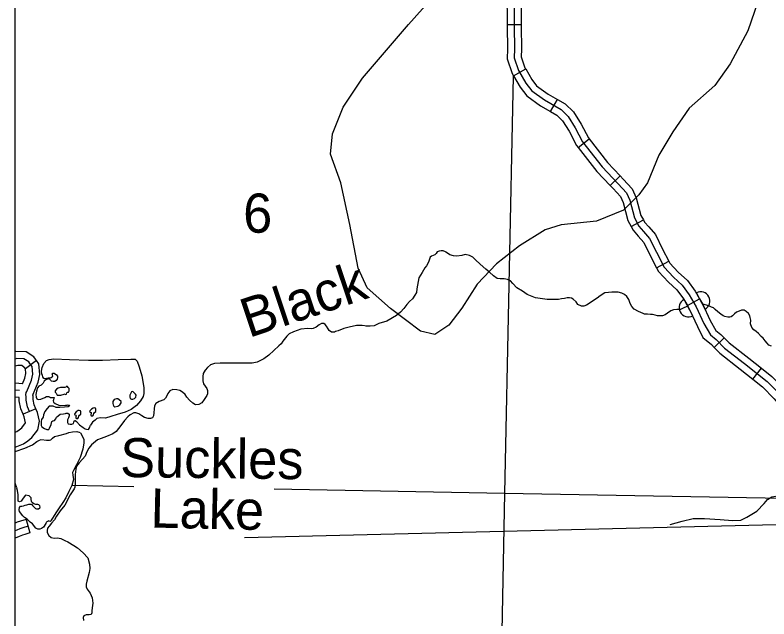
# Model space of a CAD drawing. Extents: x 8749 to 11879, y 13275 to 15339.
# Drawn here: x 9678.1 to 9840.8, y 13844.4 to 13974.8 of the extents above; entities that cross this region are included whole.
import ezdxf

# ---------------------------------------------------------------- set-up
doc = ezdxf.new("R2010")
doc.units = 0
for name, color, linetype in [('Level 31', 7, 'Continuous'), ('Level 32', 7, 'Continuous'), ('Level 35', 7, 'Continuous'), ('Level 38', 7, 'Continuous'), ('Level 45', 7, 'Continuous'), ('Level 5', 7, 'Continuous'), ('R_Draft', 7, 'Continuous')]:
    doc.layers.add(name, color=color, linetype=linetype)

msp = doc.modelspace()

# ---------------------------------------------------------------- linework, layer by layer
at = {"layer": 'Level 31'}
msp.add_lwpolyline([(9727.58, 13861.97), (9895.28, 13866.07), (10058.91, 13870.32)], dxfattribs=at)
at = {"layer": 'Level 32'}
for p, q in [((9784.28, 13972.75), (9787.28, 13972.75)), ((9785.67, 13961.66), (9788.27, 13963.14)), ((9793.65, 13953.94), (9795.15, 13956.53)), ((9799.6, 13946.17), (9801.97, 13948.02)), ((9806.48, 13937.99), (9808.67, 13940.05)), ((9811.01, 13929.15), (9813.67, 13930.54)), ((9816.51, 13920.22), (9819.17, 13921.61)), ((9823.16, 13912.06), (9825.78, 13913.53)), ((9828.97, 13902.97), (9831.11, 13905.08)), ((9682.72, 13900.16), (9680.3, 13898.38)), ((9837.28, 13896.18), (9839.14, 13898.53)), ((9682.58, 13889.77), (9679.82, 13888.58)), ((9682.58, 13889.77), (9679.82, 13888.58))]:
    msp.add_line(p, q, dxfattribs=at)
for points in [[(9782.89, 13998.9), (9783.44, 13993.92), (9784.06, 13988.9), (9784.57, 13984.55), (9785.15, 13981.25), (9785.48, 13978.4), (9785.78, 13976.08), (9785.78, 13972.31), (9785.85, 13967.45)], [(9839.72, 13981.69), (9836.2, 13971.38), (9832.42, 13964.24), (9829.06, 13959.55), (9823.51, 13954.7), (9820, 13949.59), (9816.98, 13944.54), (9814.57, 13938.56), (9812.67, 13935.94), (9809.35, 13932.65), (9803.52, 13930.28), (9795.91, 13929.5), (9792.44, 13928.4), (9786.93, 13924.96), (9781.98, 13921.09), (9777.78, 13916.7), (9774.47, 13911.52), (9771.7, 13907.8), (9768.63, 13905.84), (9765.55, 13906.49), (9759.08, 13911.44), (9754.08, 13915.87), (9752.09, 13920.14), (9750.31, 13929.54), (9748.38, 13938.52), (9746.16, 13944.77), (9746.56, 13949.12), (9748.9, 13954.89), (9753.08, 13961.18), (9762.95, 13972.72), (9779.34, 13991.12)], [(9786.28, 13983.5), (9786.64, 13981.47), (9786.97, 13978.58), (9787.28, 13976.18), (9787.28, 13972.75)], [(9783.33, 13982.98), (9783.67, 13981.03), (9783.99, 13978.22), (9784.28, 13975.99), (9784.28, 13972.75)], [(9784.28, 13972.75), (9784.28, 13972.3), (9784.35, 13967.45), (9784.3, 13965.29), (9785.38, 13962.17), (9785.67, 13961.66)], [(9787.28, 13972.75), (9787.28, 13972.32), (9787.35, 13967.44), (9787.31, 13965.76), (9788.12, 13963.41), (9788.27, 13963.14)], [(9785.85, 13967.45), (9785.81, 13965.53), (9786.75, 13962.79), (9788.31, 13960.05), (9789.58, 13958.43), (9792.32, 13956.44), (9795.9, 13954.36), (9797.41, 13952.9), (9798.92, 13950.45), (9800.53, 13947.42), (9804.77, 13941.99), (9808.21, 13938.34)], [(9788.27, 13963.14), (9789.56, 13960.89), (9790.63, 13959.52), (9793.14, 13957.7), (9795.15, 13956.53)], [(9785.67, 13961.66), (9787.06, 13959.21), (9788.53, 13957.33), (9791.5, 13955.18), (9793.65, 13953.94)], [(9795.15, 13956.53), (9796.81, 13955.57), (9798.59, 13953.85), (9800.22, 13951.19), (9801.79, 13948.24), (9801.97, 13948.02)], [(9793.65, 13953.94), (9794.99, 13953.16), (9796.23, 13951.96), (9797.62, 13949.7), (9799.26, 13946.6), (9799.6, 13946.17)], [(9801.97, 13948.02), (9805.91, 13942.97), (9808.67, 13940.05)], [(9799.6, 13946.17), (9803.63, 13941.02), (9806.48, 13937.99)], [(9808.67, 13940.05), (9809.31, 13939.37), (9811.27, 13937.24), (9812.13, 13935.3), (9813.15, 13931.53), (9813.67, 13930.54)], [(9806.48, 13937.99), (9807.11, 13937.32), (9808.73, 13935.57), (9809.29, 13934.3), (9810.34, 13930.42), (9811.01, 13929.15)], [(9808.21, 13938.34), (9810, 13936.41), (9810.71, 13934.8), (9811.75, 13930.98), (9812.69, 13929.18), (9813.68, 13928.05), (9815, 13926.54), (9816.46, 13923.56), (9818.16, 13920.31), (9820.14, 13918.18), (9822.03, 13916.43), (9823.58, 13914.36), (9825.05, 13911.76), (9826.73, 13908.15)], [(9813.67, 13930.54), (9813.94, 13930.04), (9814.81, 13929.04), (9816.26, 13927.38), (9817.8, 13924.24), (9819.17, 13921.61)], [(9811.01, 13929.15), (9811.44, 13928.33), (9812.55, 13927.06), (9813.74, 13925.7), (9815.13, 13922.89), (9816.51, 13920.22)], [(9819.17, 13921.61), (9819.4, 13921.18), (9821.2, 13919.24), (9823.15, 13917.44), (9824.84, 13915.19), (9825.78, 13913.53)], [(9816.51, 13920.22), (9816.93, 13919.43), (9819.08, 13917.12), (9820.91, 13915.42), (9822.33, 13913.54), (9823.16, 13912.06)], [(9825.78, 13913.53), (9826.39, 13912.44), (9828.05, 13908.86), (9829.32, 13906.7), (9830.37, 13905.83), (9831.11, 13905.08)], [(9823.16, 13912.06), (9823.72, 13911.07), (9825.37, 13907.51), (9826.46, 13905.16), (9828.34, 13903.62), (9828.97, 13902.97)], [(9826.72, 13908.16), (9828.16, 13905.71), (9829.35, 13904.73), (9831.18, 13902.86), (9835.47, 13899.52), (9840.37, 13895.66)], [(9831.11, 13905.08), (9832.18, 13903.99), (9836.4, 13900.7), (9839.14, 13898.53)], [(9682.72, 13900.16), (9682.51, 13900.45), (9682.1, 13901), (9680.47, 13902.05), (9678.28, 13902.12), (9678.09, 13902.07)], [(9828.97, 13902.97), (9830.18, 13901.74), (9834.54, 13898.34), (9837.28, 13896.18)], [(9681.3, 13899.56), (9681.05, 13899.89), (9680.01, 13900.57), (9678.47, 13900.61), (9678.09, 13900.51)], [(9682.58, 13889.77), (9682.2, 13890.65), (9681.99, 13891.8), (9681.97, 13892.52), (9681.94, 13892.73), (9681.97, 13892.9), (9681.98, 13892.93), (9683.04, 13895.48), (9683.41, 13897.14), (9683.22, 13899.47), (9682.72, 13900.16)], [(9680.3, 13898.38), (9680.09, 13898.67), (9680, 13898.78), (9679.55, 13899.08), (9678.66, 13899.11), (9678.09, 13898.95)], [(9681.2, 13889.17), (9680.75, 13890.22), (9680.49, 13891.64), (9680.47, 13892.4), (9680.43, 13892.75), (9680.51, 13893.31), (9680.59, 13893.5), (9681.6, 13895.93), (9681.9, 13897.25), (9681.76, 13898.92), (9681.3, 13899.56)], [(9839.14, 13898.53), (9841.38, 13896.77), (9844.13, 13893.96), (9846.75, 13890.81)], [(9679.67, 13895.18), (9680.17, 13896.38), (9680.38, 13897.35), (9680.3, 13898.38), (9680.3, 13898.38)], [(9679.67, 13895.18), (9678.09, 13895.28)], [(9837.28, 13896.18), (9839.37, 13894.54), (9841.9, 13891.95), (9844.44, 13888.89)], [(9840.37, 13895.66), (9843.01, 13892.96), (9845.82, 13889.58), (9847.7, 13886.94), (9848.86, 13884.67), (9849.4, 13882.86), (9850.29, 13879.86), (9851.15, 13876.65), (9852.29, 13873.76), (9853.5, 13870.63), (9854.28, 13867.61)], [(9679.06, 13893.72), (9678.09, 13893.78)], [(9678.98, 13892.22), (9678.09, 13892.28)], [(9679.82, 13888.58), (9679.3, 13889.78), (9679, 13891.49), (9678.98, 13892.22)], [(9678.09, 13881.5), (9679.92, 13882.17), (9680.84, 13882.84), (9681.72, 13883.59), (9682.98, 13885.19), (9683.33, 13887.12), (9682.93, 13888.96), (9682.58, 13889.77)], [(9678.09, 13884.7), (9678.5, 13884.85), (9678.98, 13885.2), (9679.55, 13885.68), (9680.35, 13886.7), (9680.06, 13888.03), (9679.82, 13888.58)]]:
    msp.add_lwpolyline(points, dxfattribs=at)
at = {"layer": 'Level 35'}
for points in [[(9775.21, 13923.05), (9774.48, 13922.83), (9773.42, 13922.72), (9772.72, 13922.77), (9771.92, 13923.04), (9771.43, 13923.36), (9771.03, 13923.58), (9770.94, 13923.63), (9770.46, 13923.88), (9770, 13923.9), (9769.6, 13923.8), (9769.17, 13923.66), (9768.98, 13923.26), (9768.68, 13923.01), (9768.33, 13922.83), (9767.95, 13922.72), (9767.66, 13922.47), (9767.52, 13922.1), (9767.36, 13921.61), (9767.14, 13921.1), (9766.9, 13920.64), (9766.47, 13920.18), (9765.93, 13919.21), (9765.23, 13918.02), (9764.91, 13916.46), (9764.8, 13915.65), (9764.72, 13914.84), (9764.37, 13914.27), (9763.83, 13913.52), (9763.21, 13912.95)], [(9792.91, 13913.34), (9790.41, 13913.72), (9788.58, 13914.42), (9787.55, 13915.17), (9786.37, 13915.85), (9785.5, 13916.85), (9785.02, 13917.36), (9784.34, 13917.66), (9783.64, 13917.79), (9782.75, 13917.82), (9782.08, 13917.9), (9781.33, 13918.44), (9780.44, 13919.25), (9779.68, 13919.9), (9778.41, 13921), (9777.47, 13921.92), (9776.85, 13922.49), (9776.15, 13922.84), (9775.21, 13923.05)], [(9813.63, 13910.33), (9812.59, 13910.8), (9811.7, 13911.26), (9811.18, 13911.83), (9810.81, 13912.5), (9810.51, 13913.39), (9810.11, 13914.01), (9809.59, 13914.42), (9809.03, 13914.74), (9808.19, 13914.93), (9806.87, 13914.96), (9806.17, 13914.88), (9805.36, 13914.82), (9804.37, 13914.15), (9803.66, 13913.66), (9802.88, 13913.18), (9801.94, 13912.48), (9801.37, 13912.15), (9800.83, 13911.91), (9800.3, 13911.91), (9799.54, 13912.31), (9799.16, 13912.83), (9798.49, 13913.42), (9798.17, 13913.64), (9797.71, 13913.72), (9797.22, 13913.72), (9796.63, 13913.58), (9796.01, 13913.47), (9795.34, 13913.39), (9794.66, 13913.34), (9793.99, 13913.34), (9792.91, 13913.34)], [(9763.21, 13912.95), (9762.63, 13912.25), (9761.96, 13911.44), (9761.28, 13910.65), (9760.37, 13909.9), (9758.29, 13908.71), (9756.59, 13908.17), (9755.57, 13907.69), (9754.68, 13907.61), (9754.06, 13907.58), (9753.81, 13907.58)], [(9823.24, 13911.91), (9822.42, 13911.55), (9821.69, 13911.17), (9820.91, 13911.17), (9820.13, 13911.14), (9819.56, 13910.95), (9818.89, 13910.44), (9818.38, 13910.06), (9817.76, 13909.87), (9817.19, 13909.85), (9816.71, 13909.87), (9816.19, 13909.98), (9815.65, 13910.09), (9815.17, 13910.09), (9814.58, 13910.22), (9814.33, 13910.2), (9813.88, 13910.2), (9813.63, 13910.33)], [(9836.65, 13909.83), (9836.38, 13910.36), (9835.87, 13910.79), (9835.38, 13911.09), (9834.85, 13911.09), (9834.33, 13910.87), (9833.79, 13910.65), (9833.34, 13910.28), (9832.93, 13909.85), (9832.58, 13909.63), (9832.31, 13909.58), (9831.88, 13909.58), (9831.26, 13909.71), (9830.88, 13909.85), (9830.37, 13910.22), (9829.72, 13910.71), (9829.13, 13911.19), (9828.78, 13911.55), (9828.35, 13911.73), (9827.92, 13911.9), (9826.34, 13912.46)], [(9841.32, 13903.25), (9840.75, 13903.52), (9840.35, 13903.92), (9839.94, 13904.41), (9839.48, 13905), (9839.11, 13905.38), (9838.51, 13906.03), (9838.03, 13906.43), (9837.52, 13906.84), (9837.08, 13907.35), (9836.81, 13908.13), (9836.84, 13908.91), (9836.73, 13909.48), (9836.65, 13909.83)], [(9754.06, 13907.58), (9752.98, 13907.73), (9751.76, 13907.73), (9750.2, 13907.38), (9749.04, 13907.09), (9747.83, 13906.6), (9747.24, 13906.47), (9746.99, 13906.33), (9746.35, 13906.33), (9745.86, 13906.65), (9745.65, 13907.06), (9745.32, 13907.6), (9745.03, 13907.98), (9744.7, 13908.19), (9744.22, 13908.19), (9743.71, 13907.9), (9743.06, 13907.41), (9742.44, 13907.09), (9741.95, 13907.01), (9741.23, 13907.09), (9739.74, 13906.98), (9738.18, 13906.36), (9737.26, 13905.93), (9736.7, 13905.47), (9735.83, 13904.39), (9735.51, 13903.77), (9735.03, 13903.36)], [(9735.03, 13903.36), (9732.85, 13901.37), (9731.74, 13900.56), (9730.29, 13899.84), (9729.26, 13899.65), (9727.19, 13899.59), (9725.98, 13899.65), (9724.12, 13899.65)], [(9683.96, 13897.11), (9683.88, 13897.25), (9683.8, 13897.92), (9683.91, 13898.65), (9684.26, 13899.54), (9684.85, 13900.16), (9685.42, 13900.41), (9686.42, 13900.54), (9689.84, 13900.41), (9693.94, 13900.27), (9696.93, 13900.27), (9700.3, 13900.41), (9703.1, 13900.46)], [(9703.1, 13900.46), (9704.01, 13900.49), (9704.45, 13900.03), (9704.88, 13898.79), (9705.42, 13896.87), (9705.85, 13894.39), (9705.87, 13893.07), (9705.69, 13892.44), (9705.15, 13891.5), (9704.31, 13890.45), (9703.15, 13889.58), (9701.83, 13889.04), (9700.11, 13888.53), (9698.73, 13888.1), (9697.57, 13887.75), (9696.55, 13887.78), (9695.74, 13887.67), (9695.34, 13887.29), (9694.77, 13886.89), (9694.39, 13886.21)], [(9724.12, 13899.65), (9722.31, 13899.6), (9721.1, 13899.52), (9720.24, 13899.25), (9719.62, 13898.68), (9719.08, 13898.12), (9718.65, 13897.39), (9718.62, 13896.71), (9718.62, 13895.82), (9718.78, 13895.12), (9719.48, 13894.18), (9719.62, 13893.74), (9719.62, 13893.02), (9719.48, 13892.64), (9718.89, 13891.75), (9718.38, 13891.02), (9717.71, 13890.72), (9717.03, 13890.64), (9716.41, 13890.97), (9715.71, 13891.64), (9715.12, 13892.31), (9714.79, 13892.85), (9714.2, 13893.39), (9713.66, 13893.69), (9712.96, 13893.85), (9712.13, 13893.91), (9711.45, 13893.61), (9711.02, 13893.04), (9710.81, 13892.56), (9710.54, 13892.04), (9710.16, 13891.72)], [(9683.88, 13897.25), (9684.1, 13896.49), (9684.42, 13896.3), (9685.23, 13896.44), (9685.69, 13896.44), (9685.87, 13896.55), (9686.2, 13896.79), (9686.14, 13897.11), (9686.09, 13897.33), (9686.23, 13897.46), (9686.55, 13897.44), (9687.01, 13897.09), (9687.22, 13896.82), (9687.22, 13896.55), (9687.2, 13896.14), (9686.98, 13895.9), (9686.63, 13895.66), (9686.28, 13895.63), (9685.96, 13895.76), (9685.71, 13895.93), (9685.63, 13896.06), (9685.23, 13896.22), (9684.74, 13896.01), (9684.37, 13895.76), (9684.15, 13895.33), (9683.69, 13894.9), (9683.21, 13894.68), (9682.91, 13894.28), (9682.72, 13893.55), (9682.56, 13892.85), (9682.61, 13892.28), (9682.75, 13891.91), (9683.1, 13891.74), (9683.66, 13891.82), (9684.5, 13892.23), (9684.9, 13892.42), (9685.28, 13892.44), (9685.52, 13892.34), (9685.74, 13892.2), (9686.12, 13892.18), (9686.52, 13892.23), (9686.31, 13891.47), (9686.41, 13891.18), (9686.76, 13890.91), (9687.55, 13890.58), (9687.98, 13890.47), (9688.95, 13890.58), (9689.35, 13890.58), (9689.54, 13890.61), (9689.76, 13890.58)], [(9688.52, 13894.33), (9687.92, 13894.39), (9687.36, 13894.23), (9687.01, 13894.01), (9686.76, 13893.66), (9686.74, 13893.34), (9686.93, 13893.15), (9687.17, 13892.74), (9687.3, 13892.74), (9687.95, 13892.74), (9688.68, 13892.9), (9688.92, 13892.98), (9689, 13892.88), (9689.19, 13892.9), (9689.16, 13893.04), (9689.32, 13893.36), (9689.62, 13893.39), (9689.76, 13893.61), (9689.78, 13894.06), (9689.76, 13894.17), (9689.59, 13894.28), (9689.54, 13894.39), (9689.43, 13894.6), (9689.22, 13894.68), (9689.06, 13894.44), (9688.84, 13894.36), (9688.52, 13894.33)], [(9703.13, 13893.25), (9702.87, 13892.68), (9702.86, 13892.34), (9702.93, 13892.01), (9703.2, 13891.81), (9703.53, 13891.81), (9703.84, 13892.01), (9704.15, 13892.31), (9704.18, 13892.74), (9704.09, 13892.94), (9703.78, 13893.21), (9703.58, 13893.45), (9703.4, 13893.51), (9703.23, 13893.43), (9703.13, 13893.25)], [(9689.76, 13890.58), (9689.81, 13890.39), (9689.56, 13890.17), (9688.78, 13890.09), (9687.73, 13890.06), (9686.92, 13890.06), (9686.33, 13890.31), (9685.87, 13890.33), (9685.47, 13890.33), (9685.04, 13889.85), (9684.52, 13889.15), (9684.23, 13888.44), (9684.12, 13887.93), (9683.82, 13887.47), (9683.74, 13886.99), (9683.74, 13886.39), (9683.69, 13886.15), (9683.85, 13885.85), (9684.44, 13885.48), (9684.93, 13885.26), (9685.36, 13885.29), (9685.49, 13885.58), (9685.9, 13886.34), (9686.03, 13886.99), (9686.22, 13887.18), (9686.57, 13887.23), (9686.87, 13887.58), (9687.06, 13887.98), (9687.41, 13888.25), (9687.81, 13888.58), (9688.54, 13888.71), (9688.94, 13888.77), (9689.13, 13888.79), (9689.46, 13888.85), (9689.73, 13888.63), (9689.73, 13888.23), (9689.62, 13887.8), (9689.43, 13887.36), (9689.38, 13886.8), (9689.56, 13886.5), (9689.99, 13886.45), (9690.35, 13886.45), (9690.67, 13886.58), (9690.8, 13886.85), (9690.83, 13887.09), (9690.88, 13887.23), (9691.07, 13887.23), (9691.32, 13887.01), (9692.02, 13886.31), (9692.8, 13885.75), (9693.23, 13885.42), (9693.5, 13885.34), (9693.96, 13885.31), (9694.12, 13885.66), (9694.39, 13886.21)], [(9699.62, 13890.19), (9700.24, 13890.34), (9700.67, 13890.61), (9701, 13891.04), (9701, 13891.37), (9700.56, 13891.72), (9700.24, 13891.91), (9699.97, 13891.93), (9699.46, 13891.77), (9699.19, 13891.34), (9699.16, 13890.93), (9699.22, 13890.61), (9699.32, 13890.45), (9699.41, 13890.31), (9699.62, 13890.19)], [(9710.16, 13891.72), (9709.19, 13891.32), (9708.46, 13890.89), (9708.19, 13890.41), (9708.08, 13889.76), (9708.05, 13888.89), (9707.95, 13888.25), (9707.73, 13887.84), (9707.3, 13887.65), (9706.84, 13887.68), (9706.03, 13887.87), (9705.41, 13888.25), (9704.82, 13888.68), (9704.39, 13888.84), (9704.12, 13888.89), (9703.71, 13888.92), (9702.91, 13888.47), (9702.42, 13888.06), (9701.73, 13887.25), (9700.9, 13886.13), (9699.91, 13884.89)], [(9691.34, 13887.66), (9691.64, 13887.69), (9691.76, 13887.89), (9691.82, 13888.17), (9691.97, 13888.42), (9692.24, 13888.63), (9692.25, 13888.82), (9692.27, 13889.09), (9692.17, 13889.31), (9691.94, 13889.43), (9691.67, 13889.36), (9691.3, 13889.09), (9690.96, 13888.77), (9690.88, 13888.56), (9691, 13888.45), (9691.22, 13888.39), (9691.25, 13888.22), (9691.19, 13888), (9691.2, 13887.81), (9691.23, 13887.71), (9691.34, 13887.66)], [(9694.6, 13888.22), (9694.89, 13888.25), (9695.02, 13888.45), (9695.08, 13888.73), (9695.23, 13888.97), (9695.49, 13889.19), (9695.51, 13889.38), (9695.53, 13889.65), (9695.43, 13889.87), (9695.2, 13889.99), (9694.93, 13889.91), (9694.56, 13889.65), (9694.22, 13889.33), (9694.14, 13889.11), (9694.26, 13889.01), (9694.48, 13888.94), (9694.51, 13888.77), (9694.45, 13888.56), (9694.46, 13888.37), (9694.49, 13888.27), (9694.6, 13888.22)], [(9692.17, 13884.58), (9692.92, 13883.2), (9692.92, 13882.39), (9692.73, 13881.07), (9692.11, 13879.23), (9691.36, 13877.64), (9690.66, 13876.45), (9690.49, 13875.99), (9690.55, 13875.4), (9690.68, 13874.48), (9690.36, 13873.2), (9689.68, 13871.91), (9689.03, 13870.53), (9688.39, 13869.5), (9687.62, 13868.39), (9686.89, 13867.32), (9686.33, 13866.37), (9685.86, 13865.73), (9685.78, 13865.51), (9685.71, 13865.46), (9685.23, 13865.57), (9685.16, 13865.46), (9684.78, 13865.3), (9684.73, 13865.03), (9684.19, 13864.2), (9683.77, 13863.89), (9683.46, 13863.75), (9683.03, 13863.75), (9682.54, 13863.98), (9681.81, 13864.9), (9681.33, 13865.28), (9680.71, 13865.9), (9680.12, 13866.33), (9679.74, 13866.65), (9679.06, 13867.6), (9678.96, 13867.97), (9679.01, 13868.43), (9679.23, 13868.73), (9679.52, 13868.76), (9679.87, 13868.78), (9680.25, 13868.97), (9680.63, 13869), (9681.06, 13869.19), (9681.33, 13869.19), (9681.6, 13869.19), (9681.87, 13868.89), (9682.19, 13868.51), (9682.46, 13868.24), (9682.73, 13868.14), (9683.16, 13868.19), (9683.43, 13868.41), (9683.49, 13868.54), (9683.43, 13868.81), (9683.22, 13869), (9682.97, 13869.11), (9682.57, 13869.13), (9682.16, 13869.27), (9681.84, 13869.46), (9681.68, 13869.62), (9681.63, 13869.81), (9681.54, 13870.19), (9681.54, 13870.51), (9681.38, 13870.7), (9681.11, 13870.94), (9680.34, 13871.11)], [(9683.76, 13883.1), (9683.79, 13883.1), (9684.87, 13882.99), (9685.49, 13882.99), (9685.81, 13883.07), (9686.16, 13883.42), (9686.62, 13883.78), (9687.51, 13883.99), (9689.18, 13884.45), (9689.69, 13884.67), (9690.5, 13884.77), (9691.39, 13884.88), (9692.13, 13884.62)], [(9699.91, 13884.89), (9699.21, 13884.34), (9697.83, 13883.8), (9696.68, 13883.35), (9695.84, 13883.08), (9694.57, 13882), (9694.03, 13881.27), (9693.58, 13880.49), (9693.2, 13879.57), (9692.66, 13878.87), (9691.88, 13878.11), (9691.34, 13877.41), (9691.2, 13876.76), (9691.07, 13875.57), (9691.04, 13874.44), (9691.04, 13873.55), (9690.96, 13872.82), (9690.84, 13872.47)], [(9678.09, 13880.51), (9680.19, 13881.26), (9681.86, 13882.01), (9682.81, 13882.67), (9683.08, 13882.87), (9683.34, 13883), (9683.7, 13883.1)], [(9678.45, 13872.69), (9678.09, 13873.74)], [(9680.34, 13871.11), (9679.82, 13870.44), (9679.39, 13869.85), (9679.04, 13869.71), (9678.77, 13869.82), (9678.72, 13870.28), (9678.72, 13871.2), (9678.61, 13872.11), (9678.45, 13872.64)], [(9690.84, 13872.47), (9690, 13871.16), (9688.84, 13868.95), (9687.79, 13867.76), (9687.01, 13866.55), (9686.61, 13865.77), (9685.93, 13865.08), (9685.42, 13864.4), (9685.1, 13864), (9684.99, 13863.51), (9685.01, 13863.03), (9685.37, 13862.41), (9685.85, 13862), (9686.5, 13861.84), (9687.25, 13861.87), (9687.93, 13861.79), (9688.82, 13861.33), (9689.44, 13861.06), (9690.73, 13860.27), (9691.54, 13859.71), (9692.78, 13858.68), (9693.78, 13857.58), (9694.18, 13856.2), (9694.23, 13855.28), (9694.1, 13854.45), (9693.59, 13852.58), (9693.43, 13851.91), (9693.43, 13851.34), (9693.61, 13850.8), (9694.29, 13849.97), (9694.7, 13848.96), (9694.83, 13847.8), (9694.7, 13846.77), (9694.67, 13846.11)], [(9819.42, 13864.79), (9822.02, 13865.5), (9824.42, 13866.07), (9826.83, 13866.07), (9830.23, 13865.88), (9832.87, 13865.64), (9834.71, 13865.74), (9835.98, 13866.35), (9838.15, 13867.67), (9839.75, 13869.32), (9840.46, 13870.17), (9841.4, 13870.79), (9843.06, 13871.02), (9845.46, 13870.46), (9848.76, 13869.23), (9851.22, 13867.62), (9852.83, 13867.21)], [(9694.67, 13846.11), (9694.67, 13845.69), (9694.48, 13845.36), (9694.1, 13845.28), (9693.43, 13845.31), (9692.91, 13845.07), (9692.81, 13844.74), (9692.83, 13844.04)]]:
    msp.add_lwpolyline(points, dxfattribs=at)
at = {"layer": 'Level 38'}
for p, q in [((9826.98, 13911.27), (9825.1, 13914.8)), ((9824.33, 13909.86), (9822.45, 13913.39))]:
    msp.add_line(p, q, dxfattribs=at)
for centre, start, end in [((9826.04, 13913.03), 298.0676, 118.0676), ((9823.39, 13911.62), 118.0676, 298.0676)]:
    msp.add_arc(centre, 2, start, end, dxfattribs=at)
at = {"layer": 'Level 45'}
msp.add_line((9680.46, 13865.85), (9681.3, 13862.97), dxfattribs=at)
for points in [[(9680.46, 13865.85), (9679.27, 13865.5), (9678.56, 13865.26), (9678.09, 13865.04)], [(9680.88, 13864.41), (9679.73, 13864.07), (9679.12, 13863.86), (9678.43, 13863.55), (9678.09, 13863.42)], [(9681.3, 13862.97), (9680.18, 13862.64), (9679.67, 13862.47), (9678.99, 13862.16), (9678.09, 13861.83)]]:
    msp.add_lwpolyline(points, dxfattribs=at)
at = {"layer": 'Level 5'}
for points in [[(9785.58, 13961.6), (9783.7, 13871.5)], [(9678.21, 13873.39), (9678.09, 13873.39)], [(9703.73, 13872.93), (9690.35, 13873.17)], [(9783.7, 13871.5), (9733.98, 13872.39)], [(9783.7, 13871.5), (9781.84, 13774.52)], [(9852.03, 13870.28), (9783.7, 13871.5)]]:
    msp.add_lwpolyline(points, dxfattribs=at)
at = {"layer": 'R_Draft'}
msp.add_lwpolyline([(9678.09, 14456.3), (10959.72, 14456.3), (10959.72, 13439.87), (9678.09, 13439.87)], close=True, dxfattribs=at)

# ---------------------------------------------------------------- texts
at = {"layer": 'Level 35'}
for s, rotation, p in [('Black', 18.4525, (9728.49, 13905.02)), ('Suckles ', 359.2831, (9700.72, 13875.04)), ('Lake', 358.6967, (9707.24, 13864.14))]:
    msp.add_text(s, height=8.448, rotation=rotation, dxfattribs=at).set_placement(p)
at = {"layer": 'Level 5'}
msp.add_text('6', height=8.45, dxfattribs=at).set_placement((9727.3, 13927.78))

doc.saveas('drawing.dxf')
